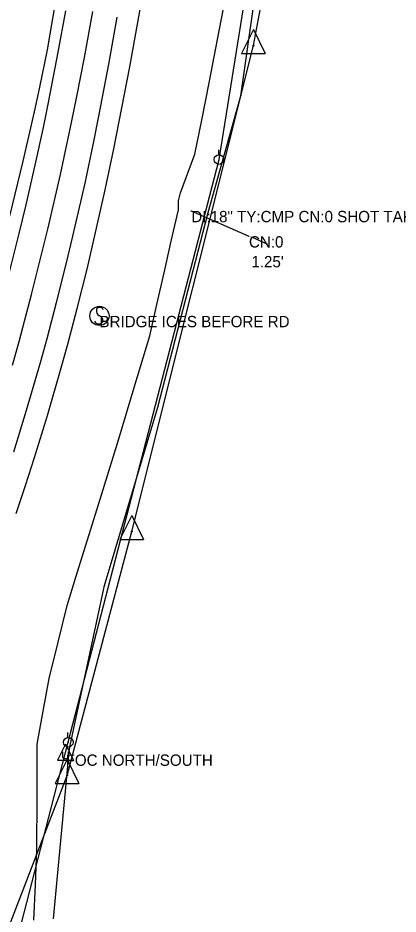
# Model space of a CAD drawing. Extents: x 1674300 to 1677920, y 225056 to 231852.
# Drawn here: x 1677403.3 to 1677571.2, y 228323.9 to 228719.7 of the extents above; entities that cross this region are included whole.
import ezdxf

# ---------------------------------------------------------------- set-up
doc = ezdxf.new("R2010")
doc.units = 0
for name, color, linetype in [('S_CROSS_DRAIN', 7, 'Continuous'), ('S_CROSS_DRAIN_ANNOT', 7, 'Continuous'), ('S_DITCHLINE', 7, 'Continuous'), ('S_DRG_PT_SYM', 7, 'Continuous'), ('S_DROP_INLET_ANNOT', 7, 'Continuous'), ('S_EDGE_PAVEMENT', 7, 'Continuous'), ('S_ELECTRIC_UTILITIES', 7, 'Continuous'), ('S_EXIST_ROW', 7, 'Continuous'), ('S_FIBER_OPTIC_CABLE', 7, 'Continuous'), ('S_MSC_PT_SYM', 7, 'Continuous'), ('S_PAVEMENT_CROWN', 7, 'Continuous'), ('S_SHOULDER', 7, 'Continuous'), ('S_SIGN', 7, 'Continuous'), ('S_SIGN_ANNOT', 7, 'Continuous'), ('S_UNDERGROUND_CABLE', 7, 'Continuous'), ('S_UTILITY_POLE', 7, 'Continuous'), ('S_UTILITY_POLE_ANNOT', 7, 'Continuous'), ('S_UTL_PT_SYM', 7, 'Continuous')]:
    doc.layers.add(name, color=color, linetype=linetype)

msp = doc.modelspace()

# ---------------------------------------------------------------- linework, layer by layer
at = {"layer": 'S_CROSS_DRAIN'}
msp.add_line((1677479.85, 228634.45), (1677505.31, 228623.28), dxfattribs=at)
at = {"layer": 'S_DITCHLINE'}
for points in [[(1677410.29, 228321.3), (1677410.97, 228336.87), (1677411.65, 228352.45), (1677411.72, 228375.7), (1677411.79, 228398.95), (1677414.39, 228413.46), (1677417, 228427.97), (1677421, 228444.05), (1677425, 228460.14), (1677429.48, 228474.66), (1677433.97, 228489.17), (1677440.9, 228511.49), (1677447.83, 228533.8), (1677454.65, 228556.51), (1677461.47, 228579.22), (1677464.64, 228593.16), (1677467.81, 228607.09), (1677470.98, 228621.03), (1677474.15, 228634.96), (1677474.23, 228638.85), (1677475, 228642.39), (1677481.44, 228659.54), (1677484.58, 228675.24), (1677487.72, 228690.94), (1677492.32, 228714.69), (1677496.91, 228738.44)], [(1677513.71, 228619.62), (1677506.9, 228622.64)]]:
    msp.add_lwpolyline(points, dxfattribs=at)
at = {"layer": 'S_DRG_PT_SYM'}
for points in [[(1677479.85, 228634.45), (1677479.85, 228634.5), (1677479.85, 228634.45), (1677479.8, 228634.45), (1677479.85, 228634.45), (1677479.85, 228634.4), (1677479.85, 228634.45), (1677479.9, 228634.45)], [(1677505.31, 228623.28), (1677505.31, 228623.33), (1677505.31, 228623.28), (1677505.26, 228623.28), (1677505.31, 228623.28), (1677505.31, 228623.23), (1677505.31, 228623.28), (1677505.36, 228623.28)], [(1677506.24, 228623.01), (1677506.24, 228623.06), (1677506.24, 228623.01), (1677506.19, 228623.01), (1677506.24, 228623.01), (1677506.24, 228622.96), (1677506.24, 228623.01), (1677506.29, 228623.01)]]:
    msp.add_lwpolyline(points, dxfattribs=at)
at = {"layer": 'S_EDGE_PAVEMENT'}
for points in [[(1677397.76, 228600.29), (1677403.84, 228624.42), (1677406.74, 228636.52), (1677410.91, 228654.71), (1677414.49, 228671.28), (1677416.78, 228682.34), (1677421.11, 228704.51), (1677424.43, 228722.78)], [(1677401.47, 228528.12), (1677407.09, 228546.47), (1677413.2, 228567.53), (1677416.13, 228578.1), (1677420.36, 228594), (1677424.77, 228611.51), (1677427.58, 228623.22), (1677432.9, 228646.7), (1677436.65, 228664.42), (1677439.04, 228676.26), (1677443.55, 228699.98), (1677447.09, 228720.05)]]:
    msp.add_lwpolyline(points, dxfattribs=at)
at = {"layer": 'S_ELECTRIC_UTILITIES'}
for p, q in [((1677492.08, 228657.14), (1677537.01, 228935.14)), ((1677425.49, 228399.8), (1677492.08, 228657.14)), ((1677343.16, 228080.48), (1677425.49, 228399.8))]:
    msp.add_line(p, q, dxfattribs=at)
at = {"layer": 'S_EXIST_ROW'}
for p, q in [((1677507.28, 228707.44), (1677527.92, 228816.46)), ((1677507.3, 228714.54), (1677502.01, 228703.9)), ((1677507.3, 228714.54), (1677512.53, 228703.9)), ((1677453.53, 228492.88), (1677507.28, 228707.44)), ((1677502.01, 228703.9), (1677512.53, 228703.9)), ((1677507.28, 228707.44), (1677507.28, 228707.44)), ((1677453.55, 228499.97), (1677448.26, 228489.33)), ((1677453.55, 228499.97), (1677458.78, 228489.33)), ((1677424.97, 228385.14), (1677453.53, 228492.88)), ((1677453.53, 228492.88), (1677453.53, 228492.88)), ((1677448.26, 228489.33), (1677458.78, 228489.33)), ((1677424.99, 228392.23), (1677419.7, 228381.6)), ((1677424.99, 228392.23), (1677430.22, 228381.6)), ((1677344.31, 228175.41), (1677424.97, 228385.14)), ((1677424.97, 228385.14), (1677424.97, 228385.14)), ((1677419.7, 228381.6), (1677430.22, 228381.6))]:
    msp.add_line(p, q, dxfattribs=at)
for centre, radius in [((1677507.28, 228707.44), 0.18), ((1677507.28, 228707.44), 0.09), ((1677453.53, 228492.88), 0.18), ((1677453.53, 228492.88), 0.09), ((1677424.97, 228385.14), 0.18), ((1677424.97, 228385.14), 0.09)]:
    msp.add_circle(centre, radius, dxfattribs=at)
at = {"layer": 'S_FIBER_OPTIC_CABLE'}
for p, q in [((1677501.74, 228685.3), (1677511.42, 228753.9)), ((1677487.34, 228633.72), (1677501.74, 228685.3)), ((1677465.1, 228547.8), (1677487.34, 228633.72)), ((1677441.54, 228468.97), (1677465.1, 228547.8)), ((1677425.99, 228396.98), (1677441.54, 228468.97)), ((1677419.05, 228321.79), (1677425.99, 228396.98))]:
    msp.add_line(p, q, dxfattribs=at)
at = {"layer": 'S_MSC_PT_SYM'}
msp.add_lwpolyline([(1677506.24, 228623.01), (1677506.24, 228623.06), (1677506.24, 228623.01), (1677506.19, 228623.01), (1677506.24, 228623.01), (1677506.24, 228622.96), (1677506.24, 228623.01), (1677506.29, 228623.01)], dxfattribs=at)
at = {"layer": 'S_PAVEMENT_CROWN'}
msp.add_lwpolyline([(1677400.94, 228566.35), (1677403.8, 228576.72), (1677409.3, 228597.51), (1677413.73, 228615.14), (1677416.58, 228626.91), (1677422.04, 228650.52), (1677426.99, 228673.43), (1677429.34, 228684.91), (1677432.69, 228702.16), (1677436.31, 228722.44)], dxfattribs=at)
at = {"layer": 'S_SHOULDER'}
for points in [[(1677399.68, 228632.11), (1677405.55, 228656.41), (1677410.62, 228678.2), (1677413.01, 228689.12), (1677416.3, 228705.55), (1677417.54, 228712.44), (1677419.8, 228726.27)], [(1677402.48, 228500.84), (1677406.57, 228513.16), (1677410.53, 228525.53), (1677416.26, 228544.14), (1677422.36, 228565.08), (1677425.27, 228575.6), (1677429.45, 228591.41), (1677433.78, 228608.79), (1677436.54, 228620.41), (1677441.77, 228643.7), (1677445.59, 228661.79), (1677448.04, 228673.87), (1677452.69, 228698.07), (1677455.02, 228711.19), (1677457.35, 228724.31)]]:
    msp.add_lwpolyline(points, dxfattribs=at)
at = {"layer": 'S_SIGN'}
msp.add_circle((1677439.27, 228588.08), 4.24, dxfattribs=at)
for centre, radius, start, end in [((1677440.44, 228590.33), 2.55, 167.1196, 241.9813), ((1677439.4, 228590.23), 1.62, 16.5258, 156.8957), ((1677439.01, 228586.68), 2.17, 204.641, 335.359), ((1677438.57, 228585.8), 2.38, 358.6529, 73.7063)]:
    msp.add_arc(centre, radius, start, end, dxfattribs=at)
at = {"layer": 'S_UNDERGROUND_CABLE'}
for p, q in [((1677424.33, 228398.92), (1677420.8, 228391.83)), ((1677423.13, 228393.07), (1677423.13, 228395.51)), ((1677424.33, 228398.92), (1677427.81, 228391.83)), ((1677425.49, 228395.51), (1677425.49, 228393.07)), ((1677420.8, 228391.83), (1677427.81, 228391.83)), ((1677423.75, 228392.41), (1677423.13, 228393.07)), ((1677424.95, 228392.41), (1677423.75, 228392.41)), ((1677425.49, 228393.07), (1677424.95, 228392.41))]:
    msp.add_line(p, q, dxfattribs=at)
at = {"layer": 'S_UTILITY_POLE'}
for p, q in [((1677491.96, 228659.28), (1677491.96, 228661.39)), ((1677425.36, 228401.94), (1677425.36, 228404.05))]:
    msp.add_line(p, q, dxfattribs=at)
for centre in [(1677492.08, 228657.14), (1677425.49, 228399.8)]:
    msp.add_circle(centre, 2.13, dxfattribs=at)
at = {"layer": 'S_UTL_PT_SYM'}
for points in [[(1677501.74, 228685.3), (1677501.74, 228685.35), (1677501.74, 228685.3), (1677501.69, 228685.3), (1677501.74, 228685.3), (1677501.74, 228685.25), (1677501.74, 228685.3), (1677501.79, 228685.3)], [(1677492.08, 228657.14), (1677492.08, 228657.19), (1677492.08, 228657.14), (1677492.03, 228657.14), (1677492.08, 228657.14), (1677492.08, 228657.09), (1677492.08, 228657.14), (1677492.13, 228657.14)], [(1677487.34, 228633.72), (1677487.34, 228633.77), (1677487.34, 228633.72), (1677487.29, 228633.72), (1677487.34, 228633.72), (1677487.34, 228633.67), (1677487.34, 228633.72), (1677487.39, 228633.72)], [(1677465.1, 228547.8), (1677465.1, 228547.85), (1677465.1, 228547.8), (1677465.05, 228547.8), (1677465.1, 228547.8), (1677465.1, 228547.75), (1677465.1, 228547.8), (1677465.16, 228547.8)], [(1677441.54, 228468.97), (1677441.54, 228469.02), (1677441.54, 228468.97), (1677441.49, 228468.97), (1677441.54, 228468.97), (1677441.54, 228468.92), (1677441.54, 228468.97), (1677441.59, 228468.97)], [(1677425.49, 228399.8), (1677425.49, 228399.85), (1677425.49, 228399.8), (1677425.44, 228399.8), (1677425.49, 228399.8), (1677425.49, 228399.75), (1677425.49, 228399.8), (1677425.54, 228399.8)], [(1677425.99, 228396.98), (1677425.99, 228397.03), (1677425.99, 228396.98), (1677425.94, 228396.98), (1677425.99, 228396.98), (1677425.99, 228396.93), (1677425.99, 228396.98), (1677426.04, 228396.98)]]:
    msp.add_lwpolyline(points, dxfattribs=at)

# ---------------------------------------------------------------- texts
at = {"layer": 'S_CROSS_DRAIN_ANNOT'}
for s, p in [('DI:18" TY:CMP CN:0 SHOT TAKEN AT FLOW', (1677479.85, 228629.45)), ('CN:0', (1677505.31, 228618.28))]:
    msp.add_text(s, height=5, dxfattribs=at).set_placement(p)
at = {"layer": 'S_DROP_INLET_ANNOT'}
msp.add_text("1.25'", height=5, dxfattribs=at).set_placement((1677506.38, 228609.54))
at = {"layer": 'S_SIGN_ANNOT'}
msp.add_text('BRIDGE ICES BEFORE RD', height=5, dxfattribs=at).set_placement((1677439.27, 228583.08))
at = {"layer": 'S_UTILITY_POLE_ANNOT'}
msp.add_text('FOC NORTH/SOUTH', height=5, dxfattribs=at).set_placement((1677424.33, 228389.39))

doc.saveas('drawing.dxf')
